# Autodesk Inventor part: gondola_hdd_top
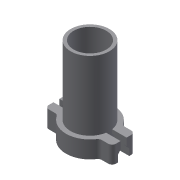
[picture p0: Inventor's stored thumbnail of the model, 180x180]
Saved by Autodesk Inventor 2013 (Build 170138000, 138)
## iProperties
Created: 2013-11
Part Number: gondola_hdd_top
Material: Generic
Document SubType Name: Modeling
Designer: Jonas
Density: 1 g/cm^3
Author: Jonas
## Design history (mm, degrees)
derived "gondola_hdd.ipt"
feature "Solid4::gondola_hdd.ipt" dims "d0" = 10
tag "TaggingFeature1"
body "Solid1"
